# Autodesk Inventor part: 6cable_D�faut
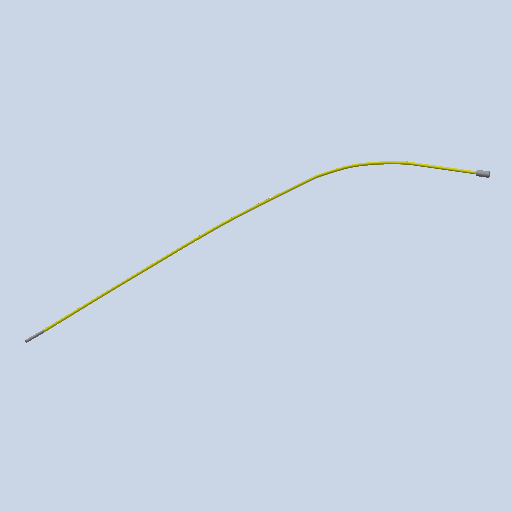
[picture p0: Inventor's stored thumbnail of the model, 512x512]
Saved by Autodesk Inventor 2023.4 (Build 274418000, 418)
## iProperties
Created: 2011-01
Part Number: 6cable_D�faut
Document SubType Name: Modeling
Designer: eric
Density: 1 g/cm^3
Mass: 1.20855 g
Surface Area: 23.4228 cm^2
Volume: 1.20855 cm^3
Material: Générique
Appearance: Par défaut
Author: eric
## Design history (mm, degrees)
feature "Base1"
node "Corps solides"
node "Corps surfaciques"
node "Solide1"
